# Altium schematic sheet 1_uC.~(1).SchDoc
size 414 x 293 mm; SheetNumber: 1; SheetTotal: 4
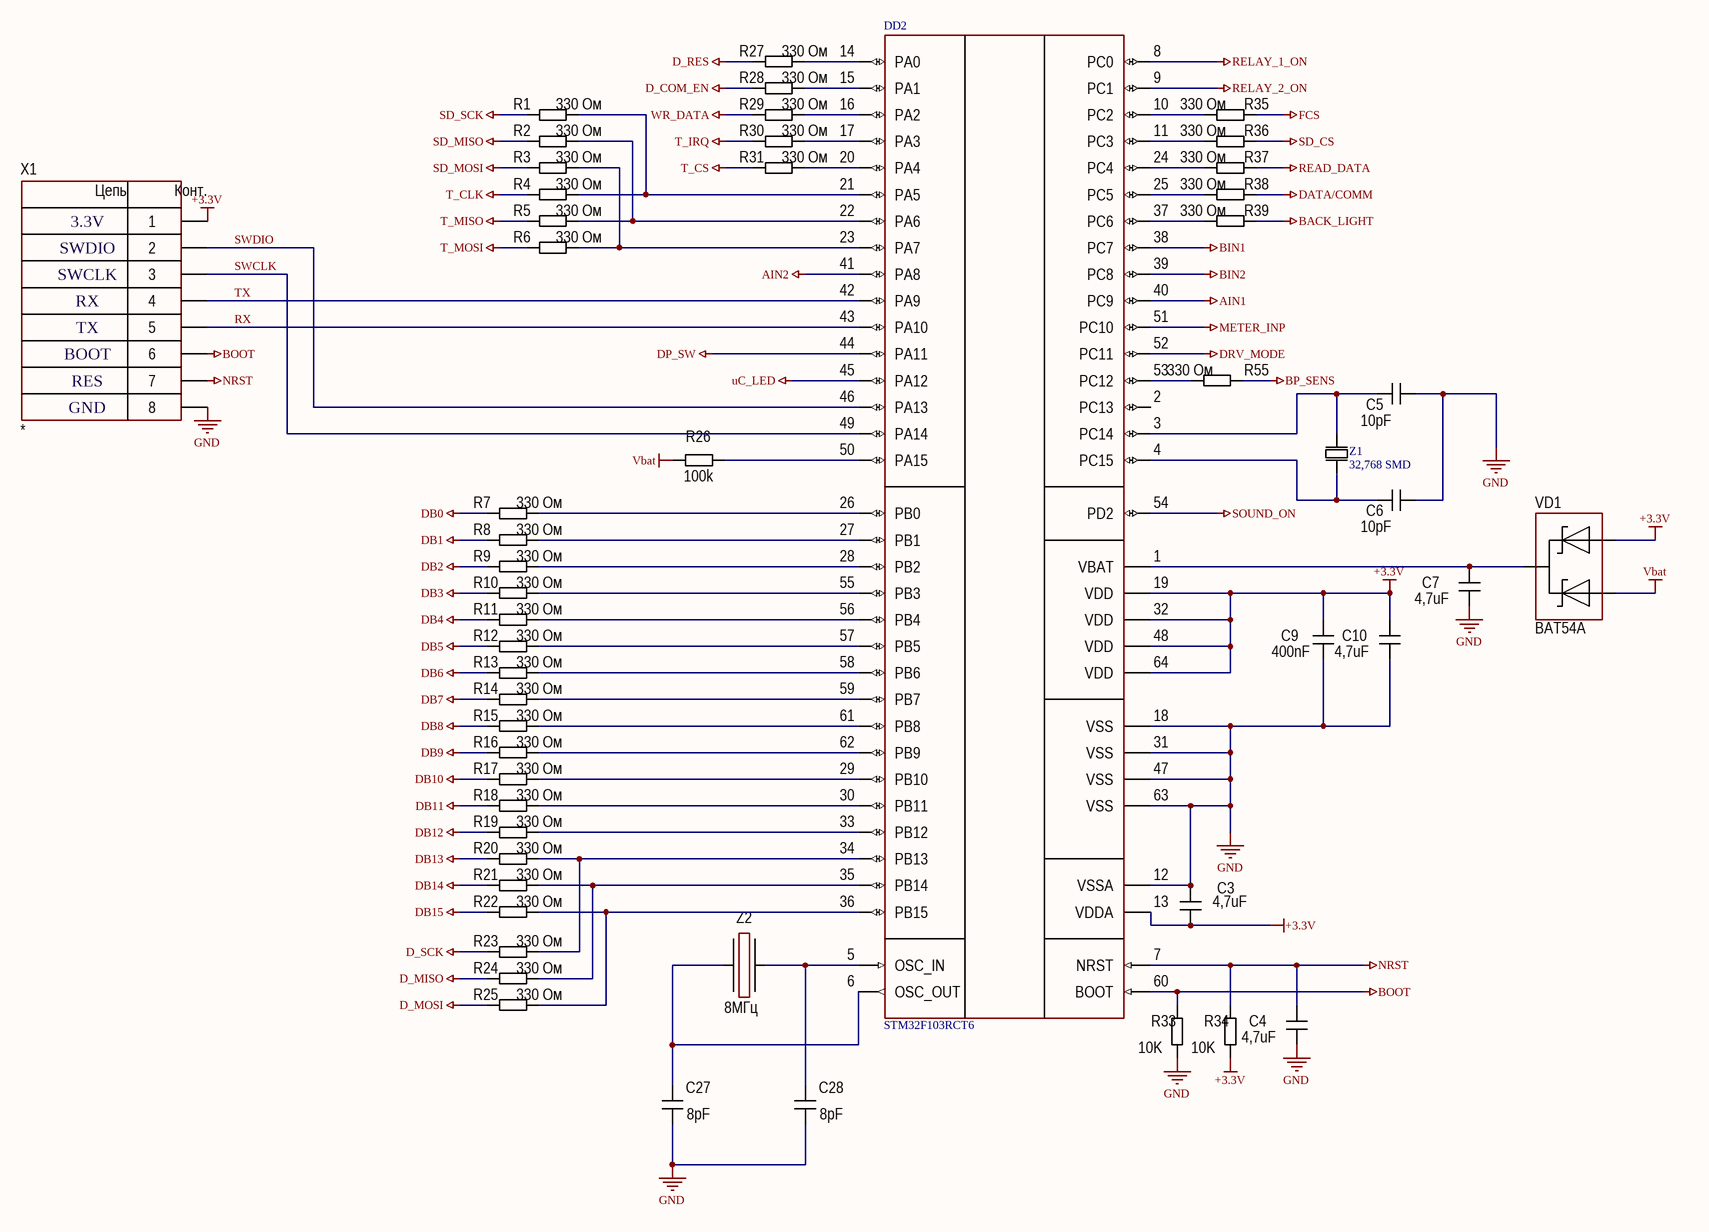
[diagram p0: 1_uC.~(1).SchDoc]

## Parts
C3  4,7uF  [CH0402C]
C4  4,7uF  [CH0402C]
C5  10pF  [CH0402C]
C6  10pF  [CH0402C]
C7  4,7uF  [CH0402C]
C9  400nF  [CH0402C]
C10  4,7uF  [CH0402C]
C27  8pF  [CH0402C]
C28  8pF  [CH0402C]
DD2  STM32F103RCT6  [64-LQFP]
R1  330 Ом  [CH0603R]
R2  330 Ом  [CH0603R]
R3  330 Ом  [CH0603R]
R4  330 Ом  [CH0603R]
R5  330 Ом  [CH0603R]
R6  330 Ом  [CH0603R]
R7  330 Ом  [CH0603R]
R8  330 Ом  [CH0603R]
R9  330 Ом  [CH0603R]
R10  330 Ом  [CH0603R]
R11  330 Ом  [CH0603R]
R12  330 Ом  [CH0603R]
R13  330 Ом  [CH0603R]
R14  330 Ом  [CH0603R]
R15  330 Ом  [CH0603R]
R16  330 Ом  [CH0603R]
R17  330 Ом  [CH0603R]
R18  330 Ом  [CH0603R]
R19  330 Ом  [CH0603R]
R20  330 Ом  [CH0603R]
R21  330 Ом  [CH0603R]
R22  330 Ом  [CH0603R]
R23  330 Ом  [CH0603R]
R24  330 Ом  [CH0603R]
R25  330 Ом  [CH0603R]
R26  100k  [CH0603R]
R27  330 Ом  [CH0603R]
R28  330 Ом  [CH0603R]
R29  330 Ом  [CH0603R]
R30  330 Ом  [CH0603R]
R31  330 Ом  [CH0603R]
R33  10K  [CH0805R]
R34  10K  [CH0805R]
R35  330 Ом  [CH0603R]
R36  330 Ом  [CH0603R]
R37  330 Ом  [CH0603R]
R38  330 Ом  [CH0603R]
R39  330 Ом  [CH0603R]
R55  330 Ом  [CH0603R]
VD1  BAT54A  [SOT23_123]
X1  *  [CON: PLS-8]
Z1  32,768 SMD  [SMD 32.768KHz]
Z2  8МГц  [OSC: ABM3]

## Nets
+3.3V: C3.1 C9.1 C10.2 DD2.13(VDDA) DD2.19(VDD) DD2.32(VDD) DD2.48(VDD) DD2.64(VDD) R34.1 VD1.1 X1.1
AIN1: DD2.40(PC9)
AIN2: DD2.41(PA8)
BACK_LIGHT: R39.1
BIN1: DD2.38(PC7)
BIN2: DD2.39(PC8)
BOOT: DD2.60(BOOT) R33.2 X1.6
BP_SENS: R55.1
D_COM_EN: R28.1
D_MISO: R24.1
D_MOSI: R25.1
D_RES: R27.1
D_SCK: R23.1
DATA/COMM: R38.1
DB0: R7.1
DB1: R8.1
DB2: R9.1
DB3: R10.1
DB4: R11.1
DB5: R12.1
DB6: R13.1
DB7: R14.1
DB8: R15.1
DB9: R16.1
DB10: R17.1
DB11: R18.1
DB12: R19.1
DB13: R20.1
DB14: R21.1
DB15: R22.1
DP_SW: DD2.44(PA11)
DRV_MODE: DD2.52(PC11)
FCS: R35.1
GND: C3.2 C4.1 C5.2 C6.1 C7.1 C9.2 C10.1 C27.1 C28.1 DD2.12(VSSA) DD2.18(VSS) DD2.31(VSS) DD2.47(VSS) DD2.63(VSS) R33.1 X1.8
METER_INP: DD2.51(PC10)
NRST: C4.2 DD2.7(NRST) R34.2 X1.7
READ_DATA: R37.1
RELAY_1_ON: DD2.8(PC0)
RELAY_2_ON: DD2.9(PC1)
SD_CS: R36.1
SD_MISO: R2.1
SD_MOSI: R3.1
SD_SCK: R1.1
SOUND_ON: DD2.54(PD2)
T_CLK: R4.1
T_CS: R31.1
T_IRQ: R30.1
T_MISO: R5.1
T_MOSI: R6.1
uC_LED: DD2.45(PA12)
Vbat: R26.1 VD1.3
WR_DATA: R29.1
RX: DD2.43(PA10) X1.5
SWCLK: DD2.49(PA14) X1.3
SWDIO: DD2.46(PA13) X1.2
TX: DD2.42(PA9) X1.4
NetC5_1: C5.1 DD2.3(PC14) Z1.1
NetC6_2: C6.2 DD2.4(PC15) Z1.2
NetC7_2: C7.2 DD2.1(VBAT) VD1.2
NetC27_2: C27.2 DD2.6(OSC_OUT) Z2.1
NetC28_2: C28.2 DD2.5(OSC_IN) Z2.3
NetDD2_10: DD2.10(PC2) R35.2
NetDD2_11: DD2.11(PC3) R36.2
NetDD2_14: DD2.14(PA0) R27.2
NetDD2_15: DD2.15(PA1) R28.2
NetDD2_16: DD2.16(PA2) R29.2
NetDD2_17: DD2.17(PA3) R30.2
NetDD2_20: DD2.20(PA4) R31.2
NetDD2_21: DD2.21(PA5) R1.2 R4.2
NetDD2_22: DD2.22(PA6) R2.2 R5.2
NetDD2_23: DD2.23(PA7) R3.2 R6.2
NetDD2_24: DD2.24(PC4) R37.2
NetDD2_25: DD2.25(PC5) R38.2
NetDD2_26: DD2.26(PB0) R7.2
NetDD2_27: DD2.27(PB1) R8.2
NetDD2_28: DD2.28(PB2) R9.2
NetDD2_29: DD2.29(PB10) R17.2
NetDD2_30: DD2.30(PB11) R18.2
NetDD2_33: DD2.33(PB12) R19.2
NetDD2_34: DD2.34(PB13) R20.2 R23.2
NetDD2_35: DD2.35(PB14) R21.2 R24.2
NetDD2_36: DD2.36(PB15) R22.2 R25.2
NetDD2_37: DD2.37(PC6) R39.2
NetDD2_50: DD2.50(PA15) R26.2
NetDD2_53: DD2.53(PC12) R55.2
NetDD2_55: DD2.55(PB3) R10.2
NetDD2_56: DD2.56(PB4) R11.2
NetDD2_57: DD2.57(PB5) R12.2
NetDD2_58: DD2.58(PB6) R13.2
NetDD2_59: DD2.59(PB7) R14.2
NetDD2_61: DD2.61(PB8) R15.2
NetDD2_62: DD2.62(PB9) R16.2

Not connected (* = marked no-connect by the designer): DD2 2(PC13)

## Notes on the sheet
- 3.3V
- SWDIO
- SWCLK
- RX
- TX
- BOOT
- RES
- GND

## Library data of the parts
C3-C6 C9 C10 C27 C28 = Capacitor: 0402
C7 = Capacitor
DD2 = STM32F103RCT6: Cortex-M3 (64-LQFP)
R1-R31 R35-R39 R55 = Resistor: 0603
R33 R34 = Resistor: 0805
VD1 = Diod Schottky Array v.1: SOT-23
X1 = 8-Connector: Pin header 8
Z1 = Kvarc_32,768: 32,768 kHz SMD 8mm x 3.8mm 12,5pF
Z2 = Oscillator: NX5032GA-8MHz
